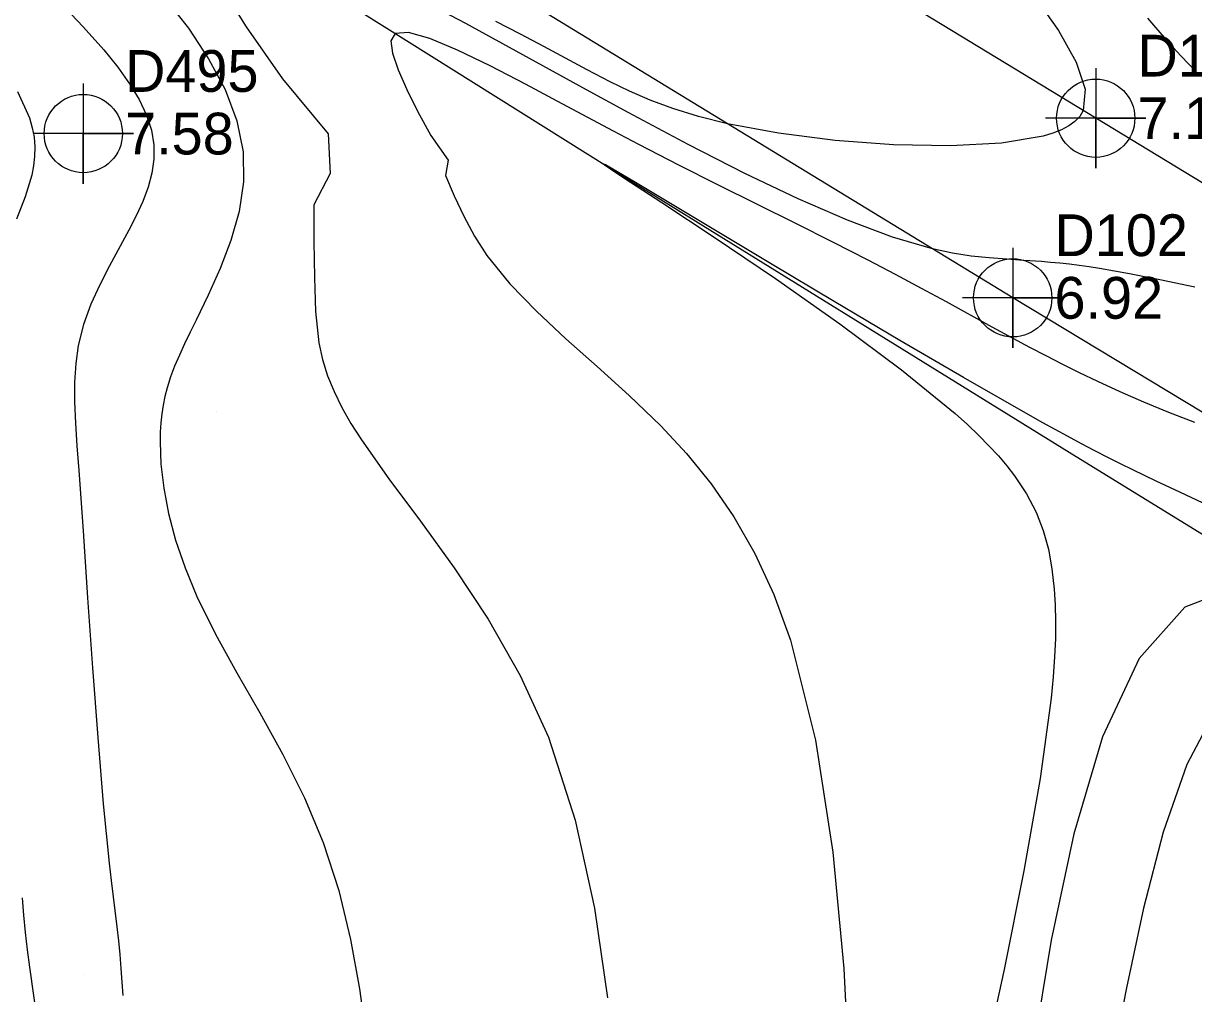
# Model space of a CAD drawing. Extents: x 2356077 to 2359823, y 225951 to 227822.
# Drawn here: x 2356980.8 to 2357050.9, y 226993.2 to 227051.3 of the extents above; entities that cross this region are included whole.
import ezdxf

# ---------------------------------------------------------------- set-up
doc = ezdxf.new("R2010")
doc.units = 0
for name, color, linetype in [('DTM Contours Major', 7, 'Continuous'), ('DTM Contours Minor', 7, 'Continuous'), ('Exist DTM Crownline', 7, 'Continuous'), ('Exist DTM Crownline Cogo Elevation', 7, 'Continuous'), ('Exist DTM Crownline Cogo Number', 7, 'Continuous'), ('Exist DTM Crownline Cogo Point CELL', 7, 'Continuous'), ('Exist DTM Regular Point CELL', 7, 'Continuous'), ('Exist DTM Regular Point Cogo Elevation', 7, 'Continuous'), ('Exist DTM Regular Point Cogo Number', 7, 'Continuous'), ('Exist Roads EOP', 7, 'Continuous'), ('Exist Roads EOP Cogo Elevation', 7, 'Continuous'), ('Exist Roads EOP Cogo Number', 7, 'Continuous'), ('Exist Roads EOP Cogo Point CELL', 7, 'Continuous'), ('PH Exist DTM Breakline', 7, 'Continuous'), ('PH Exist DTM Point', 7, 'Continuous')]:
    doc.layers.add(name, color=color, linetype=linetype)

msp = doc.modelspace()

# ---------------------------------------------------------------- linework, layer by layer
at = {"layer": 'DTM Contours Major'}
for points in [[(2356992.513, 227053.706), (2356994.143, 227051.074), (2356996.33, 227047.963), (2356999.057, 227044.671), (2356999.185, 227042.28), (2356998.199, 227040.404), (2356998.206, 227038.205), (2356998.241, 227036.054), (2356998.3, 227034.028), (2356998.504, 227032.139), (2356998.725, 227031.141), (2356999.028, 227030.174), (2356999.413, 227029.224), (2356999.88, 227028.276), (2357000.426, 227027.316), (2357001.052, 227026.329), (2357002.688, 227024.007), (2357004.581, 227021.459), (2357006.606, 227018.661), (2357008.641, 227015.59), (2357010.561, 227012.221), (2357012.242, 227008.531), (2357013.855, 227003.555), (2357015.009, 226998.276), (2357015.793, 226992.915)], [(2357050.949, 227035.469), (2357048.953, 227035.897), (2357047.037, 227036.283), (2357045.242, 227036.601), (2357044.623, 227036.695), (2357044.023, 227036.777), (2357043.439, 227036.849), (2357042.871, 227036.911), (2357042.315, 227036.964), (2357041.77, 227037.009), (2357040.723, 227037.08), (2357039.687, 227037.145), (2357038.642, 227037.225), (2357037.568, 227037.341), (2357036.445, 227037.514), (2357035.252, 227037.766), (2357032.841, 227038.474), (2357030.149, 227039.485), (2357027.2, 227040.768), (2357024.016, 227042.291), (2357020.618, 227044.022), (2357017.03, 227045.931), (2357014.526, 227047.295), (2357007.297, 227051.274), (2357002.917, 227053.595)], [(2357048.121, 227051.598), (2357048.477, 227051.164), (2357048.852, 227050.724), (2357049.248, 227050.274), (2357049.667, 227049.812), (2357050.113, 227049.334), (2357050.588, 227048.839), (2357051.142, 227048.273)]]:
    msp.add_lwpolyline(points, dxfattribs=at)
at = {"layer": 'DTM Contours Minor'}
for points in [[(2356982.967, 227052.569), (2356984.386, 227051.08), (2356985.624, 227049.687), (2356986.458, 227048.652), (2356987.165, 227047.663), (2356987.74, 227046.711), (2356988.178, 227045.788), (2356988.473, 227044.887), (2356988.621, 227043.999), (2356988.623, 227043.15), (2356988.502, 227042.304), (2356988.274, 227041.459), (2356987.958, 227040.61), (2356987.572, 227039.757), (2356987.133, 227038.896), (2356985.957, 227036.745), (2356985.379, 227035.624), (2356984.852, 227034.462), (2356984.412, 227033.248), (2356984.093, 227031.974), (2356983.944, 227030.911), (2356983.878, 227029.791), (2356983.879, 227028.602), (2356983.931, 227027.333), (2356984.019, 227025.97), (2356984.126, 227024.501), (2356984.382, 227020.875), (2356984.657, 227016.867), (2356984.951, 227012.675), (2356985.263, 227008.497), (2356985.595, 227004.528), (2356985.947, 227000.967), (2356986.063, 226999.942), (2356986.397, 226997.167), (2356986.495, 226996.318), (2356986.58, 226995.497), (2356986.654, 226994.668), (2356986.713, 226993.854), (2356986.757, 226993.047)], [(2356989.298, 227052.776), (2356990.687, 227050.982), (2356991.901, 227049.158), (2356992.888, 227047.31), (2356993.596, 227045.447), (2356993.972, 227043.578), (2356993.991, 227041.779), (2356993.722, 227040.002), (2356993.235, 227038.266), (2356992.599, 227036.592), (2356991.883, 227035), (2356991.156, 227033.51), (2356990.798, 227032.785), (2356990.46, 227032.087), (2356990.148, 227031.411), (2356989.866, 227030.75), (2356989.619, 227030.098), (2356989.412, 227029.45), (2356989.278, 227028.933), (2356989.172, 227028.412), (2356989.091, 227027.883), (2356989.035, 227027.342), (2356989.003, 227026.786), (2356988.993, 227026.213), (2356989.048, 227024.873), (2356989.216, 227023.439), (2356989.505, 227021.919), (2356989.925, 227020.323), (2356990.487, 227018.662), (2356991.199, 227016.943), (2356992.311, 227014.7), (2356993.596, 227012.378), (2356994.967, 227009.972), (2356996.343, 227007.478), (2356997.638, 227004.893), (2356998.768, 227002.211), (2356999.698, 226999.342), (2357000.405, 226996.409), (2357000.935, 226993.457), (2357001.33, 226990.53)], [(2357041.323, 227052.926), (2357042.782, 227050.847), (2357043.842, 227048.963), (2357044.378, 227047.342), (2357044.265, 227046.053), (2357044.062, 227045.706), (2357043.776, 227045.401), (2357043.411, 227045.133), (2357042.97, 227044.9), (2357042.458, 227044.698), (2357041.878, 227044.523), (2357039.376, 227044.097), (2357036.315, 227043.934), (2357032.918, 227044), (2357029.412, 227044.265), (2357026.022, 227044.697), (2357022.973, 227045.264), (2357021.236, 227045.698), (2357019.705, 227046.172), (2357018.339, 227046.681), (2357017.096, 227047.22), (2357015.935, 227047.784), (2357014.565, 227048.5), (2357011.969, 227049.886), (2357010.569, 227050.623), (2357009.1, 227051.388)], [(2357050.956, 227027.376), (2357049.403, 227027.969), (2357047.907, 227028.583), (2357046.482, 227029.204), (2357045.137, 227029.822), (2357044.051, 227030.343), (2357043.01, 227030.86), (2357042.042, 227031.355), (2357041.072, 227031.865), (2357040.075, 227032.4), (2357038.815, 227033.087), (2357036.077, 227034.593), (2357034.595, 227035.4), (2357033.035, 227036.236), (2357031.396, 227037.097), (2357029.282, 227038.177), (2357027.068, 227039.287), (2357022.429, 227041.593), (2357020.05, 227042.791), (2357017.662, 227044.018), (2357016.136, 227044.821), (2357013.079, 227046.454), (2357010.878, 227047.631), (2357008.756, 227048.733), (2357006.813, 227049.675), (2357005.151, 227050.368), (2357003.869, 227050.727), (2357003.068, 227050.663), (2357002.817, 227050.231), (2357002.905, 227049.492), (2357003.252, 227048.502), (2357003.777, 227047.322), (2357004.402, 227046.009), (2357005.215, 227044.558), (2357006.25, 227043.088), (2357006.081, 227042.169), (2357006.605, 227040.945), (2357007.174, 227039.733), (2357007.819, 227038.539), (2357008.568, 227037.373), (2357009.928, 227035.679), (2357011.527, 227034.03), (2357013.297, 227032.389), (2357015.172, 227030.723), (2357017.086, 227028.995), (2357018.973, 227027.172), (2357020.52, 227025.505), (2357021.985, 227023.702), (2357023.353, 227021.723), (2357024.613, 227019.527), (2357025.749, 227017.074), (2357026.75, 227014.324), (2357028.239, 227008.347), (2357029.275, 227001.641), (2357029.93, 226994.659), (2357030.274, 226987.859)], [(2356980.461, 227047.189), (2356981.179, 227045.617), (2356981.344, 227045.029), (2356981.446, 227044.452), (2356981.49, 227043.88), (2356981.479, 227043.313), (2356981.417, 227042.746), (2356981.309, 227042.178), (2356980.919, 227040.88), (2356980.388, 227039.553)], [(2357051.462, 227022.545), (2357050.046, 227023.196), (2357048.643, 227023.853), (2357047.244, 227024.527), (2357046.495, 227024.897), (2357045.737, 227025.28), (2357044.962, 227025.679), (2357044.161, 227026.1), (2357043.328, 227026.545), (2357041.844, 227027.358), (2357040.552, 227028.08), (2357037.095, 227030.059), (2357033.291, 227032.283), (2357029.366, 227034.609), (2357025.548, 227036.889), (2357017.369, 227041.799), (2357016.097, 227042.552), (2357015.658, 227042.801), (2357015.574, 227042.841), (2357015.567, 227042.841), (2357015.612, 227042.8), (2357015.7, 227042.736), (2357015.957, 227042.56), (2357016.753, 227042.033), (2357019.034, 227040.543), (2357022.177, 227038.471), (2357025.843, 227035.994), (2357029.695, 227033.288), (2357033.395, 227030.532), (2357036.604, 227027.901), (2357037.336, 227027.242), (2357038.01, 227026.602), (2357038.628, 227025.978), (2357039.191, 227025.368), (2357039.701, 227024.77), (2357040.158, 227024.181), (2357040.883, 227023.091), (2357041.45, 227022.007), (2357041.879, 227020.911), (2357042.189, 227019.786), (2357042.4, 227018.615), (2357042.533, 227017.38), (2357042.588, 227016.451), (2357042.612, 227015.473), (2357042.603, 227014.434), (2357042.558, 227013.326), (2357042.477, 227012.14), (2357042.356, 227010.865), (2357041.698, 227006.05), (2357040.717, 227000.52), (2357039.529, 226994.614), (2357038.247, 226988.672)], [(2357052.959, 227017.314), (2357050.358, 227016.309), (2357047.614, 227013.243), (2357045.425, 227008.544), (2357043.703, 227002.741), (2357042.355, 226996.363), (2357041.291, 226989.938)], [(2357052.174, 227010.098), (2357050.468, 227006.877), (2357049.061, 227002.837), (2357047.884, 226998.28), (2357046.87, 226993.504), (2357045.95, 226988.811)], [(2356980.731, 226998.91), (2356980.814, 226997.866), (2356980.92, 226996.831), (2356981.045, 226995.795), (2356981.184, 226994.747), (2356982.083, 226988.386)]]:
    msp.add_lwpolyline(points, dxfattribs=at)
at = {"layer": 'Exist DTM Crownline'}
msp.add_lwpolyline([(2357542.756, 226741.609), (2357459.889, 226792.427), (2357374.177, 226844.74), (2357291.426, 226895.083), (2357208.118, 226946.275), (2357125.882, 226996.539), (2357045.017, 227045.595), (2356966.337, 227093.498), (2356883.413, 227143.712), (2356799.704, 227194.618), (2356722.637, 227241.528), (2356636.765, 227293.74), (2356553.053, 227344.465), (2356470.397, 227394.758), (2356383.201, 227447.638), (2356299.889, 227498.478), (2356223.248, 227545.375)], dxfattribs=at)
at = {"layer": 'Exist DTM Crownline Cogo Point CELL'}
msp.add_lwpolyline([(2357045.017, 227048.595), (2357045.017, 227042.595), (2357045.017, 227045.595), (2357048.017, 227045.595), (2357042.017, 227045.595)], dxfattribs=at)
msp.add_circle((2357045.017, 227045.595), 2.344, dxfattribs=at)
at = {"layer": 'Exist DTM Regular Point CELL'}
msp.add_lwpolyline([(2356984.397, 227047.676), (2356984.397, 227041.676), (2356984.397, 227044.676), (2356987.397, 227044.676), (2356981.397, 227044.676)], dxfattribs=at)
msp.add_circle((2356984.397, 227044.676), 2.344, dxfattribs=at)
at = {"layer": 'Exist Roads EOP'}
msp.add_lwpolyline([(2357548.158, 226751.097), (2357551.518, 226748.955), (2357539.932, 226730.044), (2357536.732, 226732.588), (2357457.094, 226780.918), (2357368.575, 226834.971), (2357285.95, 226885.112), (2357202.56, 226936.462), (2357119.743, 226986.718), (2357040.047, 227034.838), (2356959.55, 227083.993), (2356876.77, 227134.388), (2356794.33, 227184.148), (2356716.529, 227232.438), (2356632.17, 227283.448), (2356547.589, 227334.799), (2356465.16, 227384.805), (2356376.528, 227438.798), (2356293.908, 227488.913), (2356217.843, 227535.566)], dxfattribs=at)
at = {"layer": 'Exist Roads EOP Cogo Point CELL'}
msp.add_lwpolyline([(2357040.047, 227037.838), (2357040.047, 227031.838), (2357040.047, 227034.838), (2357043.047, 227034.838), (2357037.047, 227034.838)], dxfattribs=at)
msp.add_circle((2357040.047, 227034.838), 2.344, dxfattribs=at)
at = {"layer": 'PH Exist DTM Breakline'}
msp.add_lwpolyline([(2357134.751, 226970.426), (2357100.659, 226991.809), (2357071.862, 227008.067), (2357043.428, 227025.569), (2357015.94, 227042.585), (2356988.871, 227059.572), (2356962.296, 227075.541), (2356936.875, 227090.755), (2356912.501, 227105.418), (2356894.323, 227115.538), (2356874.006, 227127.776), (2356827.187, 227157.253)], dxfattribs=at)
at = {"layer": 'PH Exist DTM Point'}
for p, q in [((2356992.347, 227028.036), (2356992.347, 227028.036)), ((2356984.49, 226994.325), (2356984.49, 226994.325))]:
    msp.add_line(p, q, dxfattribs=at)

# ---------------------------------------------------------------- texts
at = {"layer": 'Exist DTM Crownline Cogo Elevation'}
msp.add_text('7.19', height=2.5, dxfattribs=at).set_placement((2357047.517, 227044.345))
at = {"layer": 'Exist DTM Crownline Cogo Number'}
msp.add_text('D101', height=2.5, dxfattribs=at).set_placement((2357047.517, 227048.095))
at = {"layer": 'Exist DTM Regular Point Cogo Elevation'}
msp.add_text('7.58', height=2.5, dxfattribs=at).set_placement((2356986.897, 227043.426))
at = {"layer": 'Exist DTM Regular Point Cogo Number'}
msp.add_text('D495', height=2.5, dxfattribs=at).set_placement((2356986.897, 227047.176))
at = {"layer": 'Exist Roads EOP Cogo Elevation'}
msp.add_text('6.92', height=2.5, dxfattribs=at).set_placement((2357042.547, 227033.588))
at = {"layer": 'Exist Roads EOP Cogo Number'}
msp.add_text('D102', height=2.5, dxfattribs=at).set_placement((2357042.547, 227037.338))

doc.saveas('drawing.dxf')
